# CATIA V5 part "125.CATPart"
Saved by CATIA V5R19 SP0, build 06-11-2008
Part number: BekoCAB9yt1i
Nomenclature: BekoCAB9yt1i
Source: Unknown
Bounding box of the stored display mesh (mm): x -17.815 to 17.815, y -3.015 to 124.833, z -16.38 to 16.38
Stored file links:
  C:\firmalarım\oz_metal\Profil Birleştirme Kalıpları\125.CATPart
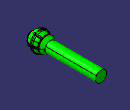
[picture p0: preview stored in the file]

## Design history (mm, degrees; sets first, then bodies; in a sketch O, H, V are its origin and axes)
Body1 "MANIFOLD_SOLID_BREP #95" (main body)
  Solid1: solid without history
